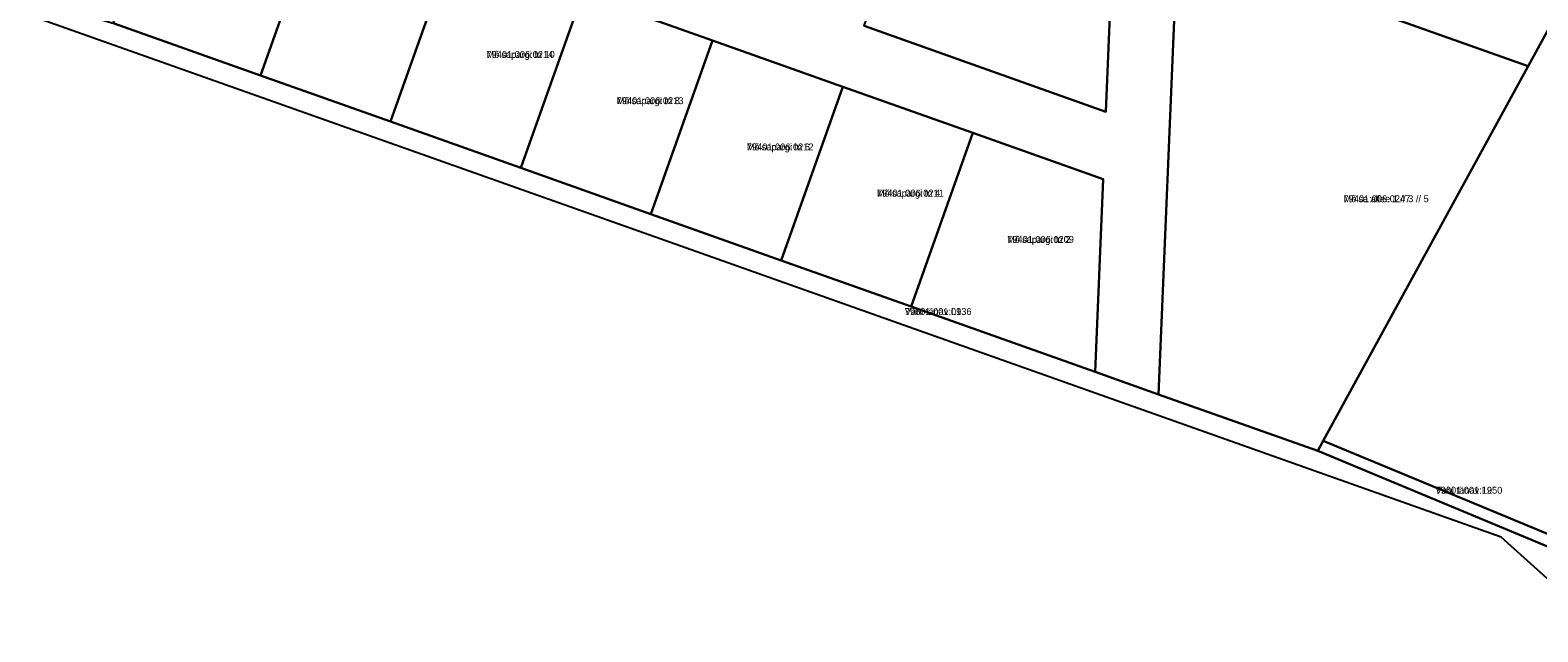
# Model space of a CAD drawing. Extents: x 625111 to 706696, y 6474150 to 6504223.
# Drawn here: x 659137.8 to 659465.2, y 6476583 to 6476713.5 of the extents above; entities that cross this region are included whole.
import ezdxf

# ---------------------------------------------------------------- set-up
doc = ezdxf.new("R2010")
doc.units = 0
for name, color, linetype in [('L_AADRESS', 7, 'Continuous'), ('PIIR', 7, 'Continuous'), ('TUNNUS', 7, 'Continuous')]:
    doc.layers.add(name, color=color, linetype=linetype)

msp = doc.modelspace()

# ---------------------------------------------------------------- linework, layer by layer
at = {"layer": 'PIIR'}
for points in [[(659386.96, 6476732.77), (659389.02, 6476782.54), (659480.92, 6476751.68), (659469.42, 6476717.2), (659463.17, 6476705.71), (659395.32, 6476729.8)], [(659145.22, 6476761.27), (659172.9, 6476751.45), (659201.17, 6476741.41), (659187.79, 6476703.72), (659156.03, 6476714.99)], [(659332.32, 6476752.16), (659373.15, 6476737.67), (659371.41, 6476695.84), (659318.94, 6476714.47)], [(659201.17, 6476741.41), (659229.44, 6476731.38), (659216.07, 6476693.68), (659187.79, 6476703.72)], [(659229.44, 6476731.38), (659257.72, 6476721.34), (659244.34, 6476683.65), (659216.07, 6476693.68)], [(659463.17, 6476705.71), (659418.62, 6476624.4), (659417.48, 6476622.22), (659382.88, 6476634.47), (659386.68, 6476726.14), (659393.92, 6476725.84), (659395.32, 6476729.8)], [(659257.72, 6476721.34), (659285.99, 6476711.31), (659272.61, 6476673.61), (659244.34, 6476683.65)], [(659138.74, 6476716.39), (659137.78, 6476720.47), (659156.03, 6476714.99), (659187.79, 6476703.72), (659216.07, 6476693.68), (659244.34, 6476683.65), (659272.61, 6476673.61), (659300.88, 6476663.58), (659329.15, 6476653.54), (659369.07, 6476639.38), (659382.88, 6476634.47), (659417.48, 6476622.22), (659467.32, 6476601.49), (659483.83, 6476587.06), (659480.14, 6476582.97), (659457.3, 6476603.51), (659274.61, 6476668.23)], [(659468.18, 6476603.88), (659418.62, 6476624.4), (659463.17, 6476705.71), (659469.42, 6476717.2), (659488.81, 6476699.12), (659516.98, 6476672.71), (659476.37, 6476626.95)], [(659285.99, 6476711.31), (659314.26, 6476701.27), (659300.88, 6476663.58), (659272.61, 6476673.61)], [(659314.26, 6476701.27), (659342.53, 6476691.24), (659329.15, 6476653.54), (659300.88, 6476663.58)], [(659342.53, 6476691.24), (659370.81, 6476681.2), (659369.07, 6476639.38), (659329.15, 6476653.54)], [(659467.32, 6476601.49), (659417.48, 6476622.22), (659418.62, 6476624.4), (659468.18, 6476603.88)]]:
    msp.add_lwpolyline(points, close=True, dxfattribs=at)
for points in [[(659318.94, 6476714.47), (659371.41, 6476695.84), (659373.15, 6476737.67)], [(659386.68, 6476726.14), (659382.88, 6476634.47), (659369.07, 6476639.38), (659370.81, 6476681.2), (659342.53, 6476691.24), (659314.26, 6476701.27), (659285.99, 6476711.31), (659257.72, 6476721.34)]]:
    msp.add_lwpolyline(points, dxfattribs=at)

# ---------------------------------------------------------------- texts
at = {"layer": 'L_AADRESS'}
for s, p in [('Mõisapargi tn 10', (659236.89, 6476707.51)), ('Mõisapargi tn 8', (659265.17, 6476697.48)), ('Mõisapargi tn 6', (659293.43, 6476687.44)), ('Mõisapargi tn 4', (659321.71, 6476677.41)), ('Mõisa allee 1 // 3 // 5', (659423.03, 6476676.2)), ('Mõisapargi tn 2', (659349.98, 6476667.37)), ('Vahi tänav L1', (659327.75, 6476651.72)), ('Vahi tänav L2', (659443.03, 6476612.94))]:
    msp.add_text(s, height=1.5, dxfattribs=at).set_placement(p)
at = {"layer": 'TUNNUS'}
for s, p in [('79401:006:0214', (659236.89, 6476707.51)), ('79401:006:0213', (659265.17, 6476697.48)), ('79401:006:0212', (659293.43, 6476687.44)), ('79401:006:0211', (659321.71, 6476677.41)), ('79401:006:0247', (659423.03, 6476676.2)), ('79401:006:0209', (659349.98, 6476667.37)), ('79601:001:0936', (659327.75, 6476651.72)), ('79601:001:1950', (659443.03, 6476612.94))]:
    msp.add_text(s, height=1.5, dxfattribs=at).set_placement(p)

doc.saveas('drawing.dxf')
